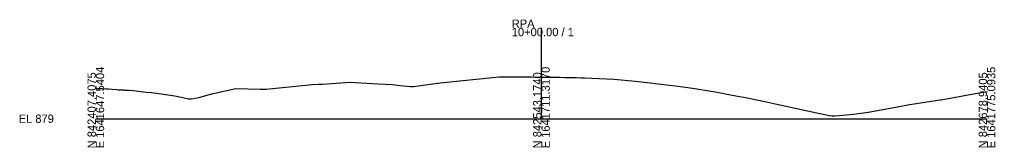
# Model space of a CAD drawing. Extents: x -26 to 303, y -10 to 6521.
# Drawn here: x -25.7 to 302.8, y -9.7 to 33.4 of the extents above; entities that cross this region are included whole.
import ezdxf

# ---------------------------------------------------------------- set-up
doc = ezdxf.new("R2010")
doc.units = 0
for name, color, linetype in [('Default', 7, 'Continuous'), ('Exist Cross Section Cell', 7, 'Continuous'), ('Exist XS Ground Line', 7, 'Continuous')]:
    doc.layers.add(name, color=color, linetype=linetype)

msp = doc.modelspace()

# ---------------------------------------------------------------- linework, layer by layer
at = {"layer": 'Exist Cross Section Cell'}
for p, q in [((150, 0), (150, 30.56)), ((0, 0), (150, 0)), ((150, 0), (300, 0))]:
    msp.add_line(p, q, dxfattribs=at)
at = {"layer": 'Exist XS Ground Line'}
msp.add_lwpolyline([(0, 10.19), (0.04, 10.19), (1.48, 10.15), (1.72, 10.14), (2.11, 10.11), (3.52, 10.05), (4.25, 10.02), (5.49, 9.9), (7.01, 9.76), (7.56, 9.74), (8.72, 9.69), (9.44, 9.65), (9.77, 9.64), (11.14, 9.55), (12.44, 9.47), (12.45, 9.47), (13.53, 9.35), (16.09, 9.06), (16.96, 8.97), (18.72, 8.78), (21.25, 8.43), (26.55, 7.66), (29.29, 7.07), (31.19, 6.65), (31.49, 6.65), (32.25, 6.66), (34.65, 7.17), (39.06, 8.36), (46.59, 10.02), (47.06, 10.11), (55.45, 9.96), (57.17, 9.92), (62.78, 10.45), (72.82, 11.45), (75.08, 11.59), (76.28, 11.66), (85.55, 12.24), (95.07, 11.74), (99.91, 11.48), (102.33, 11.2), (105.92, 10.79), (106.31, 10.79), (106.92, 10.79), (115.01, 11.93), (115.19, 11.95), (115.96, 12.03), (129.18, 13.42), (133.56, 13.88), (135.82, 14.1), (136.05, 14.13), (136.87, 14.12), (137.34, 14.12), (138.48, 14.12), (138.87, 14.11), (139.59, 14.1), (140.99, 14.09), (142.35, 14.08), (143.96, 14.07), (145.11, 14.05), (146.62, 14.03), (147.87, 14.02), (148.87, 14.01), (150.29, 14), (150.44, 14.01), (150.64, 14.01), (152.26, 13.99), (153.4, 13.98), (154.14, 13.97), (155.72, 13.95), (156.02, 13.94), (156.16, 13.94), (157.9, 13.89), (158.92, 13.87), (160.64, 13.84), (161.53, 13.83), (161.67, 13.83), (161.7, 13.83), (163.33, 13.76), (164.46, 13.71), (174.36, 13.29), (181.66, 12.58), (186.65, 12.07), (190.17, 11.64), (194.17, 11.14), (196.04, 10.92), (201.68, 10.17), (207.09, 9.29), (209.2, 8.91), (213.69, 8.05), (216.72, 7.48), (218.14, 7.22), (224.24, 6.05), (229.19, 4.9), (238.52, 2.86), (243.69, 1.72), (246.93, 1.06), (247.77, 0.9), (248.6, 0.9), (248.77, 0.9), (250.15, 1.09), (251.55, 1.23), (252.64, 1.33), (255.95, 1.6), (259.95, 2.24), (269.34, 3.82), (273.39, 4.66), (276.86, 5.2), (284.25, 6.31), (284.38, 6.33), (284.44, 6.34), (284.6, 6.37), (295.49, 8.37), (299.41, 9.05), (300, 9.16)], dxfattribs=at)

# ---------------------------------------------------------------- texts
at = {"layer": 'Default'}
msp.add_text('-', height=0.0001, dxfattribs=at).set_placement((0, 0))
at = {"layer": 'Exist Cross Section Cell'}
for s, p in [('RPA', (140, 30.56)), ('10+00.00 / 1', (140, 27.76)), ('EL 879', (-26, -1.4))]:
    msp.add_text(s, height=2.8, dxfattribs=at).set_placement(p)
for s, p in [('E 1641647.5404', (2.8, -10)), ('E 1641711.3170', (152.8, -10)), ('E 1641775.0935', (302.8, -10)), ('N 842407.4075', (0, -10)), ('N 842543.1740', (150, -10)), ('N 842678.9405', (300, -10))]:
    msp.add_text(s, height=2.8, rotation=90, dxfattribs=at).set_placement(p)

doc.saveas('drawing.dxf')
